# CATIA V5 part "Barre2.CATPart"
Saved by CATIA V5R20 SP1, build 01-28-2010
Part number: Barre2
Publications: "Plan.1", "E", "D", "axe_2_0", "axe_2_5"
Bounding box of the stored display mesh (mm): x 0 to 10, y -808.191 to -695.818, z -214.032 to 236.155
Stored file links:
  C:\Users\patrice\Desktop\IFMa\Semestre 3\IAO\projet iao\iao\Barre2.CATPart
  C:\Users\patrice\Desktop\IFMa\Semestre 3\IAO\projet iao\iao\skl_iao_755.CATProduct
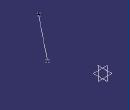
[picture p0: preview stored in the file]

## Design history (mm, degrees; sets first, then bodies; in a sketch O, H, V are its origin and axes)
Set1
  Plane1: linked copy from another document
  DatumPoint1 "E": linked copy from another document
  DatumPoint2 "D": linked copy from another document
Set2
  Plane2: type Offset, RefPlane Plane1, Offset 0
  Point1 "E": (0, 0, 0), relative to DatumPoint1
  Point2 "D": (0, 0, 0), relative to DatumPoint2
  Line1: type PtPt, FirstPoint Point1, SecondPoint Point2
  Line2 "axe_2_0": type Normal, RefPoint Point1, RefSkin Plane2, Start 0, End 10
  Line3 "axe_2_5": type Normal, RefPoint Point2, RefSkin Plane2, Start 0, End 10
Body1 (main body)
